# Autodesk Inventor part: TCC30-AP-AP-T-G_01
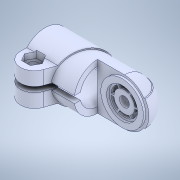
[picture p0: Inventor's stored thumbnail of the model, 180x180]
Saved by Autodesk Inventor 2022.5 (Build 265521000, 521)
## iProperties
Created: 2023-09
Part Number: TCC30-AP-AP-T-G_01
Material: 一般
Document SubType Name: Modeling
Designer: ImaoCorp
Density: 1 g/cm^3
Appearance: 既定
Author: ImaoCorp
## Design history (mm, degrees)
feature "TCC30-AP-AP-T-G_01"
node "ソリッド1"
